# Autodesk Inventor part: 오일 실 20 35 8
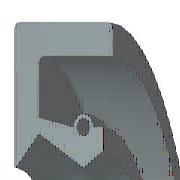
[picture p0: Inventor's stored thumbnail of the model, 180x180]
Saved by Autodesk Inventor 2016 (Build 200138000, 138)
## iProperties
Created: 2012-02
Part Number: 오일 실 20 35 8
Material: 고무
Description: 오일-실
Document SubType Name: Modeling
Standard: KS B 2804
Designer: mduedu
Standards Organization: KS
Language: ko-KR
Size Designation: D - 20 35 8
Categories: <MemberInstance><Categories><Category DisplayName="샤프트 부품" InternalName="7f7aeb1f-a693-4053-b835-cee3144e0d98" Mnemonic="SHFT"><Category DisplayName="실링" Intern
Density: 0.93 g/cm^3
Mass: 2.54606 g
Surface Area: 35.9421 cm^2
Volume: 2.7377 cm^3
Appearance: 고무 - 검은색 - 버전 1.1
IsCustomPart: 1
Author: mduedu
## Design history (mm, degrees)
revolve "본체" stored, may be unused: angle "d17" = 90 deg
revolve "스프링1" stored, may be unused: angle "d18" = 90 deg
body "Solid1"
sketch "스케치1"
  geometry: L1 (0, 17.5)-(8, 17.5); L2 (8, 15.75)-(1.75, 15.75); L3 (1.75, 11.75)-(4.9, 10); L4 (4.9, 10)-(0, 10); L5 (0, 0)-(9.586, 0) reference; L6 (4.9, 10)-(6.3, 10.875); L7 (0, 18)-(0, -3) reference; L8 (-1.941, 0)-(11.507, 0) reference; L9 (4.2, 12.1)-(1.75, 12.71); L10 (1.75, 12.71)-(1.75, 15.75); L11 (0, 17.5)-(0, 10.088); L12 (4.9, 10)-(0, 10); L13 (1.75, 11.75)-(0.152, 10.028); L14 (8, 17.5)-(8, 15.75); L15 (5.6, 12.1)-(6.3, 12.1); L16 (6.3, 12.1)-(6.3, 10.875); C1 r 0.455 at (4.9, 12.1); A1 r 0.7 centre (4.9, 12.1) between (5.6, 12.1) and (4.2, 12.1); A2 r 0.088 centre (0.088, 10.088) between (0, 10.088) and (0.152, 10.028); 1 further point
  constraints: 28 end point, 5 horizontal alignment, 5 point on line, 4 point on circle, 4 vertical alignment, 3 centre point, 3 tangent, 2 collinear, 2 horizontal, 2 perpendicular, 1 coincident, 1 parallel
  dimensions: "d0" = 35 diameter of L1 L5 (= SD2); "d1" = 1.75 distance of L1.end L2.start (= SD); "d2" = 0.91 diameter of C1 (= SPDI); "d3" = 1.4 diameter of A1 (= SPDA); "d4" = 20 diameter of L3.end L5 (= NND); "d5" = 23.5 diameter of L3.start L5 (= TKDM); "d7" = 25.42 diameter of L9.end L5 (= TKDM + 0.24 x SWDT); "d8" = 1.75 distance between parallel lines of L11 L10 (= SD); "d9" = 4.9 distance from line of L11 C1.centre (= SPDST); "d10" = 24.2 diameter of C1.centre L5 (= HLDM); "d11" = 0.0875 radius of A2 (= 0.25 x LAB); "d12" = 6.3 distance between parallel lines of L11 L16 (= SDI); "d13" = 21.75 diameter of L6.end L5 (= ABDM); "d14" = 8 distance from line of L11 L1.end (= SWDT)
fillet "모깎기1" dims "d6" = 0.3 (= RR)
other parameters: "SD2" = 35 [user parameter; used in 1 equation term], "SWDT" = 8 [user parameter; used in 2 equation terms], "RR" = 0.3 [user parameter; used in 1 equation term], "SD" = 1.75 [user parameter; used in 2 equation terms], "NND" = 20 [user parameter; used in 1 equation term], "SPDA" = 1.4 [user parameter; used in 1 equation term], "SPDI" = 0.91 [user parameter; used in 1 equation term], "TKDM" = 23.5 [user parameter; used in 2 equation terms], "HLDM" = 24.2 [user parameter; used in 1 equation term], "ABDM" = 21.75 [user parameter; used in 1 equation term], "SDI" = 6.3 [user parameter; used in 1 equation term], "SPDST" = 4.9 [user parameter; used in 1 equation term], "LAB" = 0.35 [user parameter; used in 1 equation term], "d15" = 0, "d16" = 0, "d19" = 0
